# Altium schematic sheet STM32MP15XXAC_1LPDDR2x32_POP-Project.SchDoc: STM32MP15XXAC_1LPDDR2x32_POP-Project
size A4; ApprovedBy: Not used; CheckedBy: Not used; Author: Not used; CompanyName: STMicroelectronics; DrawnBy: Not used; Engineer: Not used; Organization: Not used; Address1: Not used; Address2: Not used; Address3: Not used; Address4: Not used; DocumentNumber: Not used; Revision: Not used; SheetNumber: 1; SheetTotal: 7
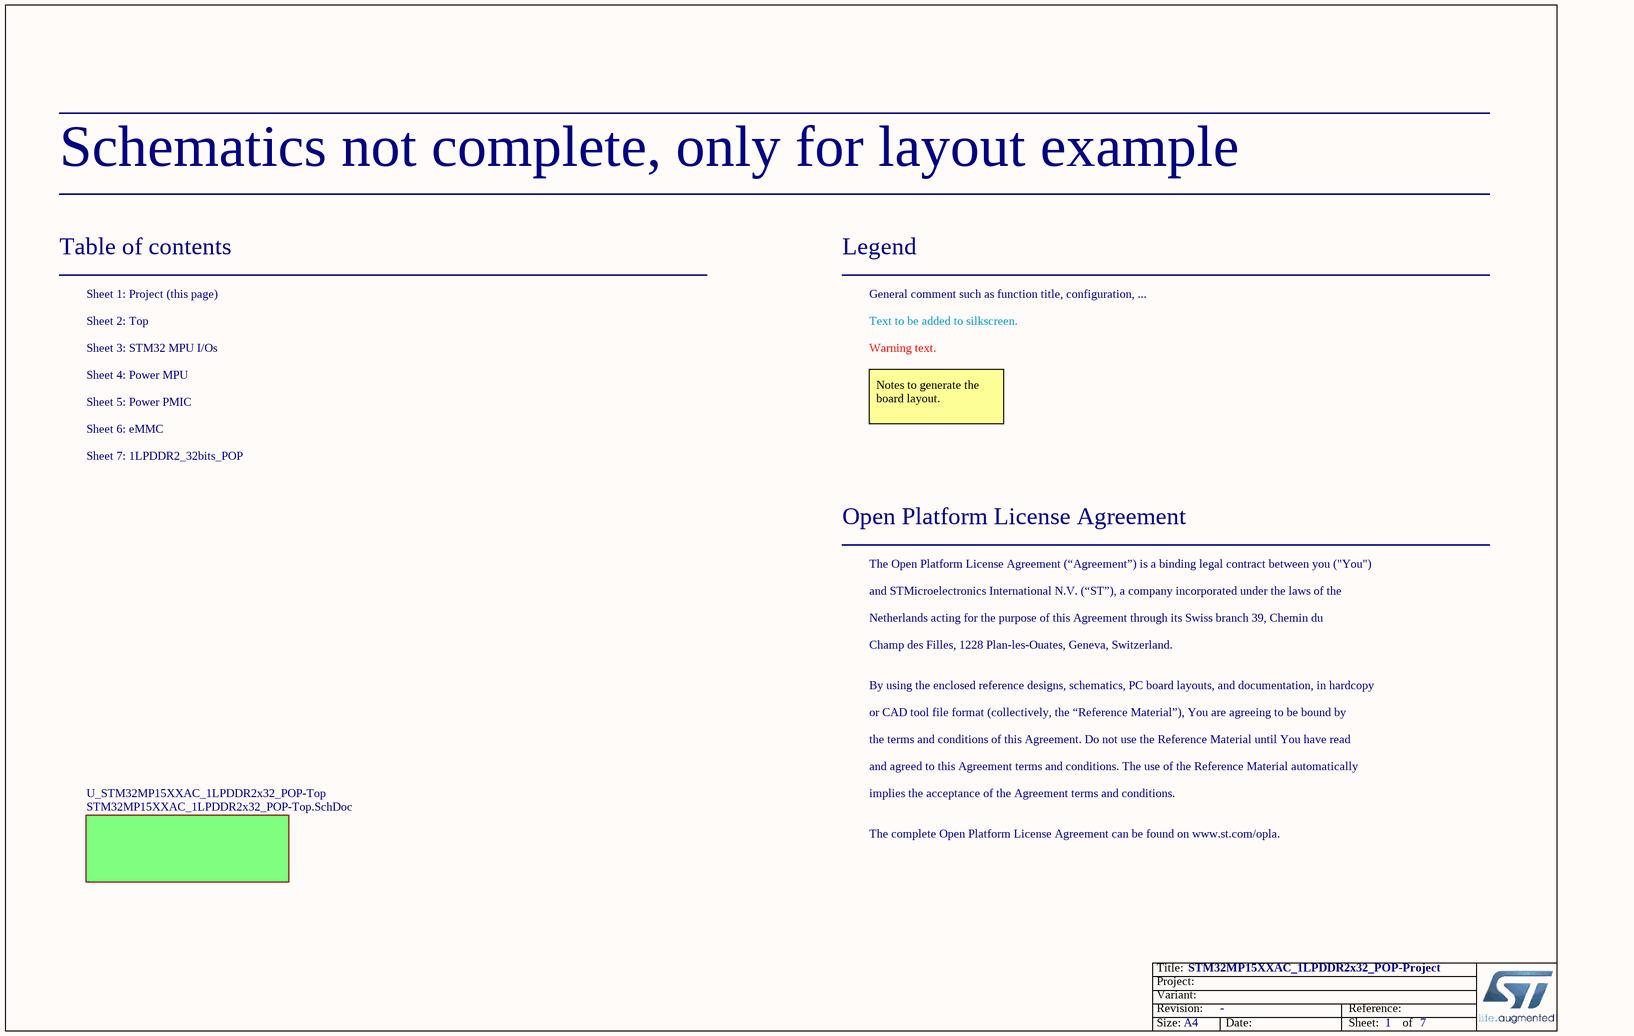
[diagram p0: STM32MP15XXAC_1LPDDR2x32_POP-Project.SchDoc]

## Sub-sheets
U_STM32MP15XXAC_1LPDDR2x32_POP-Top = STM32MP15XXAC_1LPDDR2x32_POP-Top.SchDoc: no entries

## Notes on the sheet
- Schematics not complete, only for layout example
- Table of contents
- Sheet 1: Project (this page)
- Legend
- General comment such as function title, configuration, ...
- Sheet 2: Top
- Sheet 3: STM32 MPU I/Os
- Sheet 4: Power MPU
- Text to be added to silkscreen.
- Warning text.
- Sheet 5: Power PMIC
- Sheet 6: eMMC
- Notes to generate the board layout.
- Sheet 7: 1LPDDR2_32bits_POP
- Open Platform License Agreement
- The Open Platform License Agreement (“Agreement”) is a binding legal contract between you ("You")
- and STMicroelectronics International N.V. (“ST”), a company incorporated under the laws of the
- Netherlands acting for the purpose of this Agreement through its Swiss branch 39, Chemin du
- Champ des Filles, 1228 Plan-les-Ouates, Geneva, Switzerland.
- By using the enclosed reference designs, schematics, PC board layouts, and documentation, in hardcopy
- or CAD tool file format (collectively, the “Reference Material”), You are agreeing to be bound by
- the terms and conditions of this Agreement. Do not use the Reference Material until You have read
- and agreed to this Agreement terms and conditions. The use of the Reference Material automatically
- implies the acceptance of the Agreement terms and conditions.
- The complete Open Platform License Agreement can be found on www.st.com/opla.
